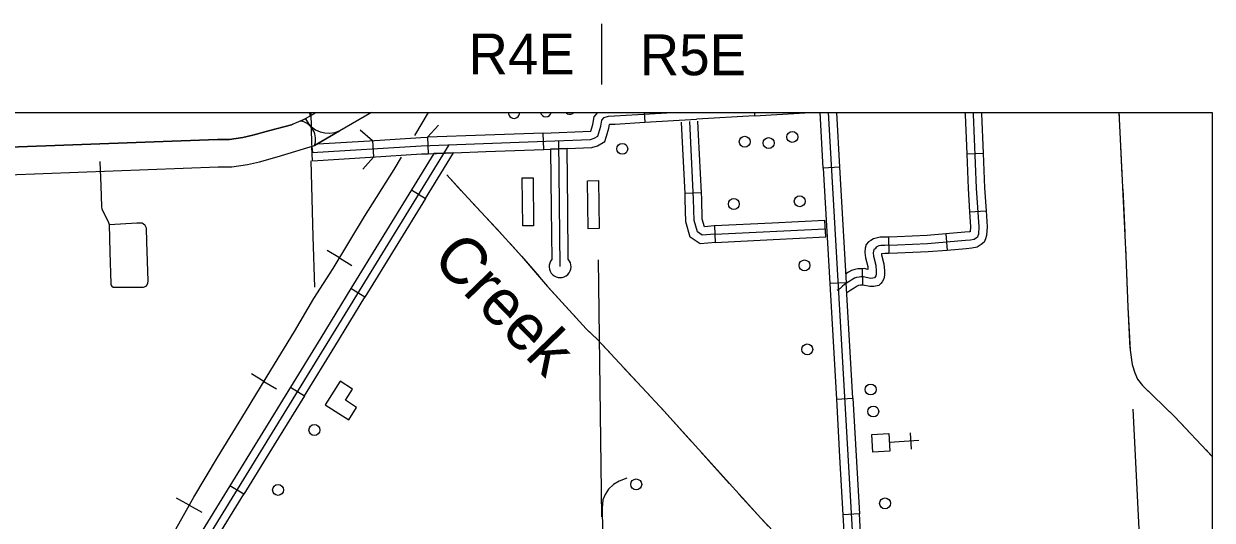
# Model space of a CAD drawing. Extents: x 309348 to 309445, y 336383 to 336484.
# Drawn here: x 309367.366 to 309372.295, y 336392.813 to 336394.873 of the extents above; entities that cross this region are included whole.
import ezdxf

# ---------------------------------------------------------------- set-up
doc = ezdxf.new("R2010")
doc.units = 0
doc.layers.add('R_Annotation', color=7, linetype='Continuous')
doc.layers.add('R_Border Notes', color=7, linetype='Continuous')

msp = doc.modelspace()

# ---------------------------------------------------------------- linework, layer by layer
at = {"layer": 'R_Annotation'}
for p, q in [((309369.7622, 336394.8727), (309369.7622, 336394.6209)), ((309369.9394, 336394.5049), (309369.9419, 336394.4638)), ((309370.3963, 336394.5049), (309370.3971, 336394.4911)), ((309368.8131, 336394.3882), (309368.8173, 336394.3201)), ((309369.0401, 336394.4015), (309369.0432, 336394.3333)), ((309369.5225, 336394.3511), (309369.52, 336394.4193)), ((309368.5642, 336394.3046), (309368.5607, 336394.3614)), ((309369.1482, 336394.3372), (309369.0664, 336394.3342)), ((309369.6194, 336394.3547), (309369.5513, 336394.3522)), ((309371.2768, 336394.3329), (309371.345, 336394.3357)), ((309370.7498, 336394.2776), (309370.6817, 336394.2737)), ((309368.9742, 336394.1838), (309369.0323, 336394.1481)), ((309370.1768, 336394.1716), (309370.1087, 336394.1683)), ((309371.2891, 336394.0923), (309371.3572, 336394.0968)), ((309370.692, 336393.9882), (309370.6886, 336394.0563)), ((309370.2307, 336394.0337), (309370.2341, 336393.9655)), ((309371.1897, 336394.0004), (309371.1956, 336393.9325)), ((309370.9522, 336393.9876), (309370.9538, 336393.9194)), ((309368.6755, 336393.9009), (309368.6241, 336393.9319)), ((309368.6755, 336393.9009), (309368.7269, 336393.8699)), ((309370.8433, 336393.8564), (309370.8446, 336393.7882)), ((309370.7771, 336393.7982), (309370.709, 336393.7944)), ((309368.7813, 336393.7388), (309368.7232, 336393.7744)), ((309368.3625, 336393.3889), (309368.3111, 336393.4199)), ((309368.3625, 336393.3889), (309368.4139, 336393.3579)), ((309368.4722, 336393.3651), (309368.5303, 336393.3294)), ((309370.7363, 336393.315), (309370.8044, 336393.3189)), ((309371.0422, 336393.1749), (309371.0463, 336393.1069)), ((309371.0783, 336393.143), (309370.9561, 336393.1355)), ((309368.2793, 336392.9201), (309368.2212, 336392.9558)), ((309368.2793, 336392.9201), (309368.2793, 336392.9201)), ((309368.0526, 336392.8749), (309368.0002, 336392.9042)), ((309368.0526, 336392.8749), (309368.105, 336392.8456))]:
    msp.add_line(p, q, dxfattribs=at)
for points in [[(309368.5155, 336394.469), (309368.5784, 336394.5049)], [(309368.5518, 336394.5049), (309368.5522, 336394.49)], [(309368.5657, 336394.3389), (309368.5613, 336394.3744), (309368.5588, 336394.5049)], [(309368.808, 336394.5049), (309368.5718, 336394.3673)], [(309369.0438, 336394.5049), (309368.9864, 336394.4089)], [(309369.0142, 336394.3664), (309369.7169, 336394.3925), (309369.7322, 336394.3974), (309369.7475, 336394.4064), (309369.7598, 336394.4473), (309369.7638, 336394.472), (309369.774, 336394.4841), (309369.7907, 336394.4895), (309369.8166, 336394.4905), (309370.0579, 336394.5049)], [(309369.718, 336394.4266), (309369.7265, 336394.4549), (309369.7316, 336394.4868), (309369.7469, 336394.5049)], [(309370.3971, 336394.4911), (309370.1574, 336394.4767)], [(309370.3971, 336394.4911), (309370.6294, 336394.5049)], [(309370.6817, 336394.2737), (309370.6685, 336394.5049)], [(309370.7027, 336394.5049), (309370.8372, 336392.1437), (309371.0852, 336387.4853)], [(309370.7368, 336394.5049), (309370.7498, 336394.2776)], [(309371.3036, 336394.5049), (309371.3042, 336394.4972), (309371.3168, 336394.1903), (309371.3274, 336394.0305), (309371.3255, 336394.0002), (309371.3232, 336393.9923), (309371.3212, 336393.9876), (309371.3173, 336393.9842), (309371.3072, 336393.9781), (309371.2932, 336393.975), (309371.2719, 336393.9733), (309371.1148, 336393.9597), (309370.9894, 336393.9544), (309370.9367, 336393.9532), (309370.9212, 336393.9527), (309370.9118, 336393.9508), (309370.9016, 336393.9461), (309370.897, 336393.9394), (309370.8913, 336393.9359), (309370.8888, 336393.9225), (309370.8906, 336393.908), (309370.9, 336393.8706), (309370.9019, 336393.846), (309370.9017, 336393.8332), (309370.9003, 336393.8263), (309370.8978, 336393.822), (309370.8944, 336393.8182), (309370.8872, 336393.8168), (309370.8781, 336393.8163), (309370.8491, 336393.8224), (309370.8372, 336393.8222), (309370.8309, 336393.8214), (309370.8201, 336393.8194), (309370.812, 336393.8171), (309370.8045, 336393.813), (309370.7923, 336393.805), (309370.7778, 336393.7959), (309370.7699, 336393.7909), (309370.7603, 336393.7826), (309370.7517, 336393.7748), (309370.7395, 336393.7654)], [(309371.2695, 336394.5049), (309371.2701, 336394.4953), (309371.2768, 336394.3329)], [(309371.3378, 336394.5049), (309371.3382, 336394.4991), (309371.345, 336394.3357)], [(309371.9078, 336394.5049), (309371.9121, 336394.423), (309371.9373, 336393.9084), (309371.9452, 336393.6961), (309371.9542, 336393.5188), (309371.9632, 336393.4586), (309371.9745, 336393.4248), (309371.9857, 336393.3983), (309372.006, 336393.3719), (309372.1388, 336393.2429), (309372.2951, 336393.0765)], [(309371.9078, 336394.5049), (309371.9088, 336394.4859)], [(309368.5344, 336394.4777), (309368.4762, 336394.4527), (309368.3875, 336394.4297), (309368.3168, 336394.4101), (309368.2742, 336394.4008), (309368.2199, 336394.3928), (309368.1703, 336394.3925), (309367.0063, 336394.3489)], [(309368.4817, 336394.4555), (309368.4762, 336394.4527), (309368.3875, 336394.4297), (309368.3168, 336394.4101), (309368.2742, 336394.4008), (309368.2199, 336394.3928), (309368.1703, 336394.3925), (309367.0063, 336394.3489)], [(309367.0063, 336394.3489), (309368.1703, 336394.3925), (309368.2199, 336394.3928), (309368.2742, 336394.4008), (309368.3168, 336394.4101), (309368.3875, 336394.4297), (309368.4762, 336394.4527), (309368.4817, 336394.4555)], [(309369.0402, 336394.4015), (309369.0863, 336394.4517)], [(309369.7832, 336394.4066), (309369.7931, 336394.4396), (309369.7956, 336394.4553), (309369.7967, 336394.4556), (309369.8183, 336394.4565), (309369.9419, 336394.4638)], [(309369.9419, 336394.4638), (309370.156, 336394.4766)], [(309370.0969, 336394.408), (309370.0941, 336394.4649)], [(309370.2324, 336393.9996), (309370.1803, 336393.9951), (309370.1599, 336394.0087), (309370.1463, 336394.0563), (309370.144, 336394.1447), (309370.1282, 336394.4666)], [(309370.165, 336394.4114), (309370.1622, 336394.4683)], [(309367.0106, 336394.2353), (309368.1727, 336394.2789), (309368.2286, 336394.2792), (309368.2946, 336394.2889), (309368.3441, 336394.2997), (309368.4169, 336394.3199), (309368.5718, 336394.3673), (309368.6762, 336394.4286)], [(309368.5855, 336394.3743), (309368.7997, 336394.3874)], [(309368.762, 336394.4331), (309368.8131, 336394.3879)], [(309368.7997, 336394.3874), (309369.0125, 336394.4004), (309369.0402, 336394.4015)], [(309369.2801, 336394.4104), (309369.0401, 336394.4015)], [(309369.52, 336394.4193), (309369.2801, 336394.4104)], [(309369.52, 336394.4193), (309369.718, 336394.4266)], [(309369.5513, 336394.3522), (309369.6194, 336394.3547), (309369.7228, 336394.3586), (309369.7463, 336394.3661), (309369.7763, 336394.3838), (309369.7832, 336394.4066)], [(309369.5906, 336393.8649), (309369.585, 336394.3876)], [(309370.1087, 336394.1683), (309370.0969, 336394.408)], [(309370.1768, 336394.1716), (309370.165, 336394.4114)], [(309371.9119, 336394.426), (309371.9121, 336394.423), (309371.9208, 336394.2461)], [(309369.1287, 336394.3706), (309367.616, 336391.9035), (309367.6109, 336391.8897), (309367.6089, 336391.8559), (309367.5998, 336391.8333), (309367.5107, 336391.6889), (309367.5033, 336391.6741), (309367.5014, 336391.6572), (309367.5035, 336391.6016), (309367.5024, 336391.591), (309367.4921, 336391.5835), (309367.4631, 336391.5792)], [(309368.5621, 336394.3387), (309369.0142, 336394.3664)], [(309369.0323, 336394.1481), (309369.1482, 336394.3372)], [(309369.0432, 336394.3333), (309369.1482, 336394.3372), (309369.2826, 336394.3422)], [(309369.2826, 336394.3422), (309369.5225, 336394.3511)], [(309369.5225, 336394.3511), (309369.5513, 336394.3522)], [(309369.5513, 336394.3522), (309369.5539, 336394.1046)], [(309369.6221, 336394.1053), (309369.6194, 336394.3547)], [(309367.2439, 336391.479), (309367.438, 336391.7957), (309367.4849, 336391.8783), (309367.5151, 336391.9444), (309367.5441, 336392.0133), (309367.5757, 336392.0822), (309367.5936, 336392.1221), (309367.6407, 336392.1987), (309367.6691, 336392.2491), (309367.7536, 336392.382), (309367.8923, 336392.6092), (309367.9917, 336392.766), (309368.0711, 336392.908), (309368.1704, 336393.0726), (309368.2866, 336393.263), (309368.3905, 336393.4353), (309368.4892, 336393.5954), (309368.5699, 336393.7328), (309368.6492, 336393.8574), (309368.7789, 336394.0723), (309368.9022, 336394.2679), (309368.9328, 336394.3192)], [(309367.5936, 336392.1221), (309367.6407, 336392.1987), (309367.6691, 336392.2491), (309367.7536, 336392.382), (309367.8923, 336392.6092), (309367.9917, 336392.766), (309368.0711, 336392.908), (309368.1704, 336393.0726), (309368.2866, 336393.263), (309368.3905, 336393.4353), (309368.4892, 336393.5954), (309368.5699, 336393.7328), (309368.6492, 336393.8574), (309368.7789, 336394.0723), (309368.9022, 336394.2679), (309368.9328, 336394.3192)], [(309367.6814, 336394.3008), (309367.6853, 336394.1996), (309367.6884, 336394.1147), (309367.6907, 336394.103), (309367.7055, 336394.0749), (309367.718, 336394.0477), (309367.7209, 336394.0396), (309367.7238, 336393.9254), (309367.7275, 336393.7953), (309367.7279, 336393.7891), (309367.7321, 336393.7837), (309367.7375, 336393.7799), (309367.7484, 336393.7791), (309367.8626, 336393.7795), (309367.8738, 336393.7837), (309367.8784, 336393.7895), (309367.8813, 336393.797), (309367.8818, 336393.8062), (309367.8763, 336393.9679), (309367.8755, 336394.025), (309367.8705, 336394.035), (309367.8622, 336394.0425), (309367.8584, 336394.045), (309367.8351, 336394.0458), (309367.7225, 336394.0379)], [(309368.5562, 336394.3042), (309368.5656, 336393.9902), (309368.5719, 336393.7798)], [(309368.5642, 336394.3046), (309368.8038, 336394.3193)], [(309368.8173, 336394.3198), (309368.7721, 336394.2687)], [(309368.8038, 336394.3193), (309369.0159, 336394.3323), (309369.0428, 336394.3333)], [(309369.0664, 336394.3342), (309368.9742, 336394.1838)], [(309371.2768, 336394.3329), (309371.2828, 336394.1885), (309371.2891, 336394.0923)], [(309371.345, 336394.3357), (309371.3509, 336394.1921), (309371.3572, 336394.0968)], [(309369.1202, 336394.2457), (309369.1924, 336394.167), (309369.3508, 336393.9966), (309369.4304, 336393.9081), (309369.539, 336393.7831), (309369.6417, 336393.6693), (309369.6982, 336393.6068), (309369.745, 336393.5633)], [(309369.1202, 336394.2457), (309369.181, 336394.1794)], [(309370.6817, 336394.2737), (309370.6954, 336394.0341)], [(309370.7498, 336394.2776), (309370.7634, 336394.0379)], [(309368.9742, 336394.1838), (309368.8487, 336393.9791)], [(309369.0323, 336394.1481), (309368.9068, 336393.9435)], [(309370.2354, 336393.9656), (309370.1713, 336393.9601), (309370.1305, 336393.9873), (309370.1123, 336394.0511), (309370.1099, 336394.1434), (309370.1087, 336394.1683)], [(309370.2295, 336394.0336), (309370.1893, 336394.0301), (309370.1892, 336394.0301), (309370.1803, 336394.0615), (309370.1781, 336394.146), (309370.1768, 336394.1716)], [(309371.9237, 336394.1862), (309371.9325, 336394.0063)], [(309369.2218, 336394.1354), (309369.3444, 336394.0035)], [(309369.5539, 336394.1046), (309369.5562, 336393.8946)], [(309369.6244, 336393.8953), (309369.6221, 336394.1053)], [(309371.2891, 336394.0923), (309371.2932, 336394.0304), (309371.2919, 336394.0096), (309371.2882, 336394.0088), (309371.2691, 336394.0073), (309371.1897, 336394.0004)], [(309371.3572, 336394.0968), (309371.3616, 336394.0305), (309371.3593, 336393.9943), (309371.3554, 336393.9808), (309371.3495, 336393.9671), (309371.3375, 336393.9565), (309371.32, 336393.946), (309371.2983, 336393.9412), (309371.2748, 336393.9393), (309371.1956, 336393.9325)], [(309370.4705, 336394.0455), (309370.2307, 336394.0337)], [(309370.6886, 336394.0563), (309370.4705, 336394.0455)], [(309370.2324, 336393.9996), (309370.6903, 336394.0223)], [(309370.6954, 336394.0341), (309370.709, 336393.7944)], [(309370.7634, 336394.0379), (309370.7771, 336393.7982)], [(309371.1897, 336394.0004), (309371.1126, 336393.9938), (309370.9883, 336393.9884), (309370.9522, 336393.9876)], [(309368.8487, 336393.9791), (309368.7232, 336393.7744)], [(309368.9068, 336393.9435), (309368.7813, 336393.7388)], [(309369.3847, 336393.959), (309369.4304, 336393.9081), (309369.5036, 336393.8238)], [(309370.2341, 336393.9655), (309370.4739, 336393.9774)], [(309370.4739, 336393.9774), (309370.692, 336393.9882)], [(309370.9522, 336393.9876), (309370.9358, 336393.9872), (309370.9174, 336393.9867), (309370.9011, 336393.9834), (309370.8901, 336393.9804), (309370.8791, 336393.9739), (309370.8701, 336393.9675), (309370.8604, 336393.9569), (309370.8558, 336393.9417), (309370.8544, 336393.9235), (309370.857, 336393.9018), (309370.8662, 336393.8651), (309370.8671, 336393.8535), (309370.8523, 336393.8566), (309370.8433, 336393.8564)], [(309371.9354, 336393.9464), (309371.9373, 336393.9084), (309371.9426, 336393.7665)], [(309369.749, 336393.8936), (309369.7621, 336392.8273)], [(309370.9538, 336393.9194), (309370.9376, 336393.9191), (309370.9251, 336393.9187), (309370.9239, 336393.9185), (309370.9237, 336393.9182), (309370.9242, 336393.9142), (309370.9338, 336393.8761), (309370.936, 336393.8471), (309370.9358, 336393.8295), (309370.9326, 336393.8139), (309370.9256, 336393.8019), (309370.921, 336393.7951), (309370.9121, 336393.7867), (309370.8913, 336393.7829), (309370.8755, 336393.782), (309370.8458, 336393.7882), (309370.8446, 336393.7882)], [(309371.1956, 336393.9325), (309371.117, 336393.9257), (309370.9905, 336393.9203), (309370.9538, 336393.9194)], [(309370.8433, 336393.8564), (309370.8347, 336393.8562), (309370.8256, 336393.8551), (309370.8123, 336393.8526), (309370.7991, 336393.8488), (309370.787, 336393.8423), (309370.775, 336393.8345)], [(309370.7908, 336393.5585), (309370.7771, 336393.7982)], [(309368.7232, 336393.7744), (309368.5977, 336393.5698)], [(309369.5431, 336393.7786), (309369.6417, 336393.6693), (309369.6637, 336393.6449)], [(309370.709, 336393.7944), (309370.7227, 336393.5547)], [(309370.8446, 336393.7882), (309370.8398, 336393.7881), (309370.8362, 336393.7877), (309370.8279, 336393.7861), (309370.825, 336393.7853), (309370.8221, 336393.7837), (309370.8106, 336393.7762), (309370.7959, 336393.7671), (309370.7795, 336393.7566)], [(309368.6558, 336393.5341), (309368.7813, 336393.7388)], [(309371.9448, 336393.7065), (309371.9452, 336393.6961), (309371.9538, 336393.5267)], [(309369.7045, 336393.6009), (309369.745, 336393.5633)], [(309368.5977, 336393.5698), (309368.4722, 336393.3651)], [(309369.745, 336393.5633), (309370.022, 336393.2654), (309370.4226, 336392.8211), (309370.6101, 336392.6253), (309370.7466, 336392.4761), (309370.7789, 336392.4412)], [(309369.745, 336393.5633), (309369.8063, 336393.4974)], [(309370.7227, 336393.5547), (309370.7363, 336393.315)], [(309370.8044, 336393.3189), (309370.7908, 336393.5585)], [(309368.5303, 336393.3294), (309368.6558, 336393.5341)], [(309369.8472, 336393.4534), (309369.9698, 336393.3215)], [(309371.9619, 336393.4672), (309371.9632, 336393.4586), (309371.9745, 336393.4248), (309371.9857, 336393.3983), (309372.006, 336393.3719), (309372.0588, 336393.3206)], [(309368.4722, 336393.3651), (309368.3467, 336393.1604)], [(309368.5303, 336393.3294), (309368.4048, 336393.1248)], [(309370.7363, 336393.315), (309370.75, 336393.0753)], [(309370.8044, 336393.3189), (309370.8181, 336393.0792)], [(309370.0106, 336393.2776), (309370.022, 336393.2654), (309370.1314, 336393.144)], [(309372.0188, 336392.2524), (309371.9672, 336393.2732)], [(309372.1019, 336393.2788), (309372.1388, 336393.2429), (309372.1652, 336393.2148)], [(309372.1652, 336393.2148), (309372.2268, 336393.1492)], [(309368.3467, 336393.1604), (309368.2212, 336392.9558)], [(309368.4048, 336393.1248), (309368.2793, 336392.9201)], [(309372.2679, 336393.1055), (309372.2951, 336393.0765)], [(309370.1716, 336393.0995), (309370.2922, 336392.9657)], [(309370.75, 336393.0753), (309370.7636, 336392.8356)], [(309370.8181, 336393.0792), (309370.8317, 336392.8395)], [(309369.8672, 336392.9876), (309369.8353, 336392.9741), (309369.8119, 336392.9608), (309369.7914, 336392.9416), (309369.7769, 336392.9194), (309369.7683, 336392.8973), (309369.765, 336392.8621), (309369.7768, 336392.1163), (309369.7879, 336392.0873), (309369.7727, 336392.0322), (309369.7761, 336392.0016), (309369.8022, 336390.1886)], [(309368.2212, 336392.9558), (309368.0957, 336392.7511)], [(309368.1539, 336392.7154), (309368.2793, 336392.9201)], [(309370.3324, 336392.9212), (309370.4226, 336392.8211), (309370.454, 336392.7884)]]:
    msp.add_lwpolyline(points, dxfattribs=at)
for points in [[(309369.4809, 336394.0345), (309369.4355, 336394.034), (309369.4333, 336394.233), (309369.4788, 336394.2334)], [(309369.752, 336394.0229), (309369.7066, 336394.0224), (309369.7044, 336394.2213), (309369.7499, 336394.2218)], [(309368.6166, 336393.2919), (309368.7139, 336393.2297), (309368.7467, 336393.281), (309368.7007, 336393.3104), (309368.73, 336393.3564), (309368.6788, 336393.3892)], [(309370.883, 336393.1681), (309370.9539, 336393.1724), (309370.9583, 336393.0989), (309370.8875, 336393.0946)], [(309370.7636, 336392.8356), (309370.7773, 336392.5959), (309370.7809, 336392.5324), (309370.849, 336392.5363), (309370.8454, 336392.5998), (309370.8317, 336392.8395), (309370.7636, 336392.8356)]]:
    msp.add_lwpolyline(points, close=True, dxfattribs=at)
for centre in [(309370.3563, 336394.3832), (309370.4554, 336394.3777), (309370.5536, 336394.4031), (309369.8485, 336394.3537), (309370.3112, 336394.1247), (309370.5845, 336394.1364), (309370.6041, 336393.8698), (309370.6157, 336393.5215), (309370.8787, 336393.3552), (309370.8892, 336393.2638), (309368.5716, 336393.1869), (309368.4209, 336392.9383), (309369.9062, 336392.9613), (309370.9385, 336392.8825)]:
    msp.add_circle(centre, 0.0227, dxfattribs=at)
for centre, radius, start, end in [((309369.3995, 336394.5023), 0.0227, 173.3254, 6.6746), ((309369.5316, 336394.5089), 0.0227, 190.091, 349.909), ((309369.6309, 336394.5203), 0.0227, 222.5738, 317.4262), ((309368.4996, 336394.3938), 0.0769, 339.8983, 78.0639), ((309368.6304, 336394.5257), 0.1073, 206.5343, 295.2244), ((309369.5906, 336393.8649), 0.0455, 139.2116, 42.0304)]:
    msp.add_arc(centre, radius, start, end, dxfattribs=at)
at = {"layer": 'R_Border Notes'}
for p, q in [((309354.7401, 336394.5049), (309372.2951, 336394.5049)), ((309372.2951, 336394.5049), (309372.2951, 336384.9236))]:
    msp.add_line(p, q, dxfattribs=at)

# ---------------------------------------------------------------- texts
at = {"layer": 'R_Annotation'}
for s, p in [('R4E', (309369.2105, 336394.6626)), ('R5E', (309369.9208, 336394.659))]:
    msp.add_text(s, height=0.16963, dxfattribs=at).set_placement(p)
msp.add_text('Creek', height=0.19206, rotation=314.1025, dxfattribs=at).set_placement((309369.0536, 336393.8914))

doc.saveas('drawing.dxf')
